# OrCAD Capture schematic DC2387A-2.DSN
size Custom; company: ANALOG DEVICES; note: DEMO BOARD BILL OF MATERIALS; note: 60VIN, 5A STEP-DOWN µMODULE REGULATOR
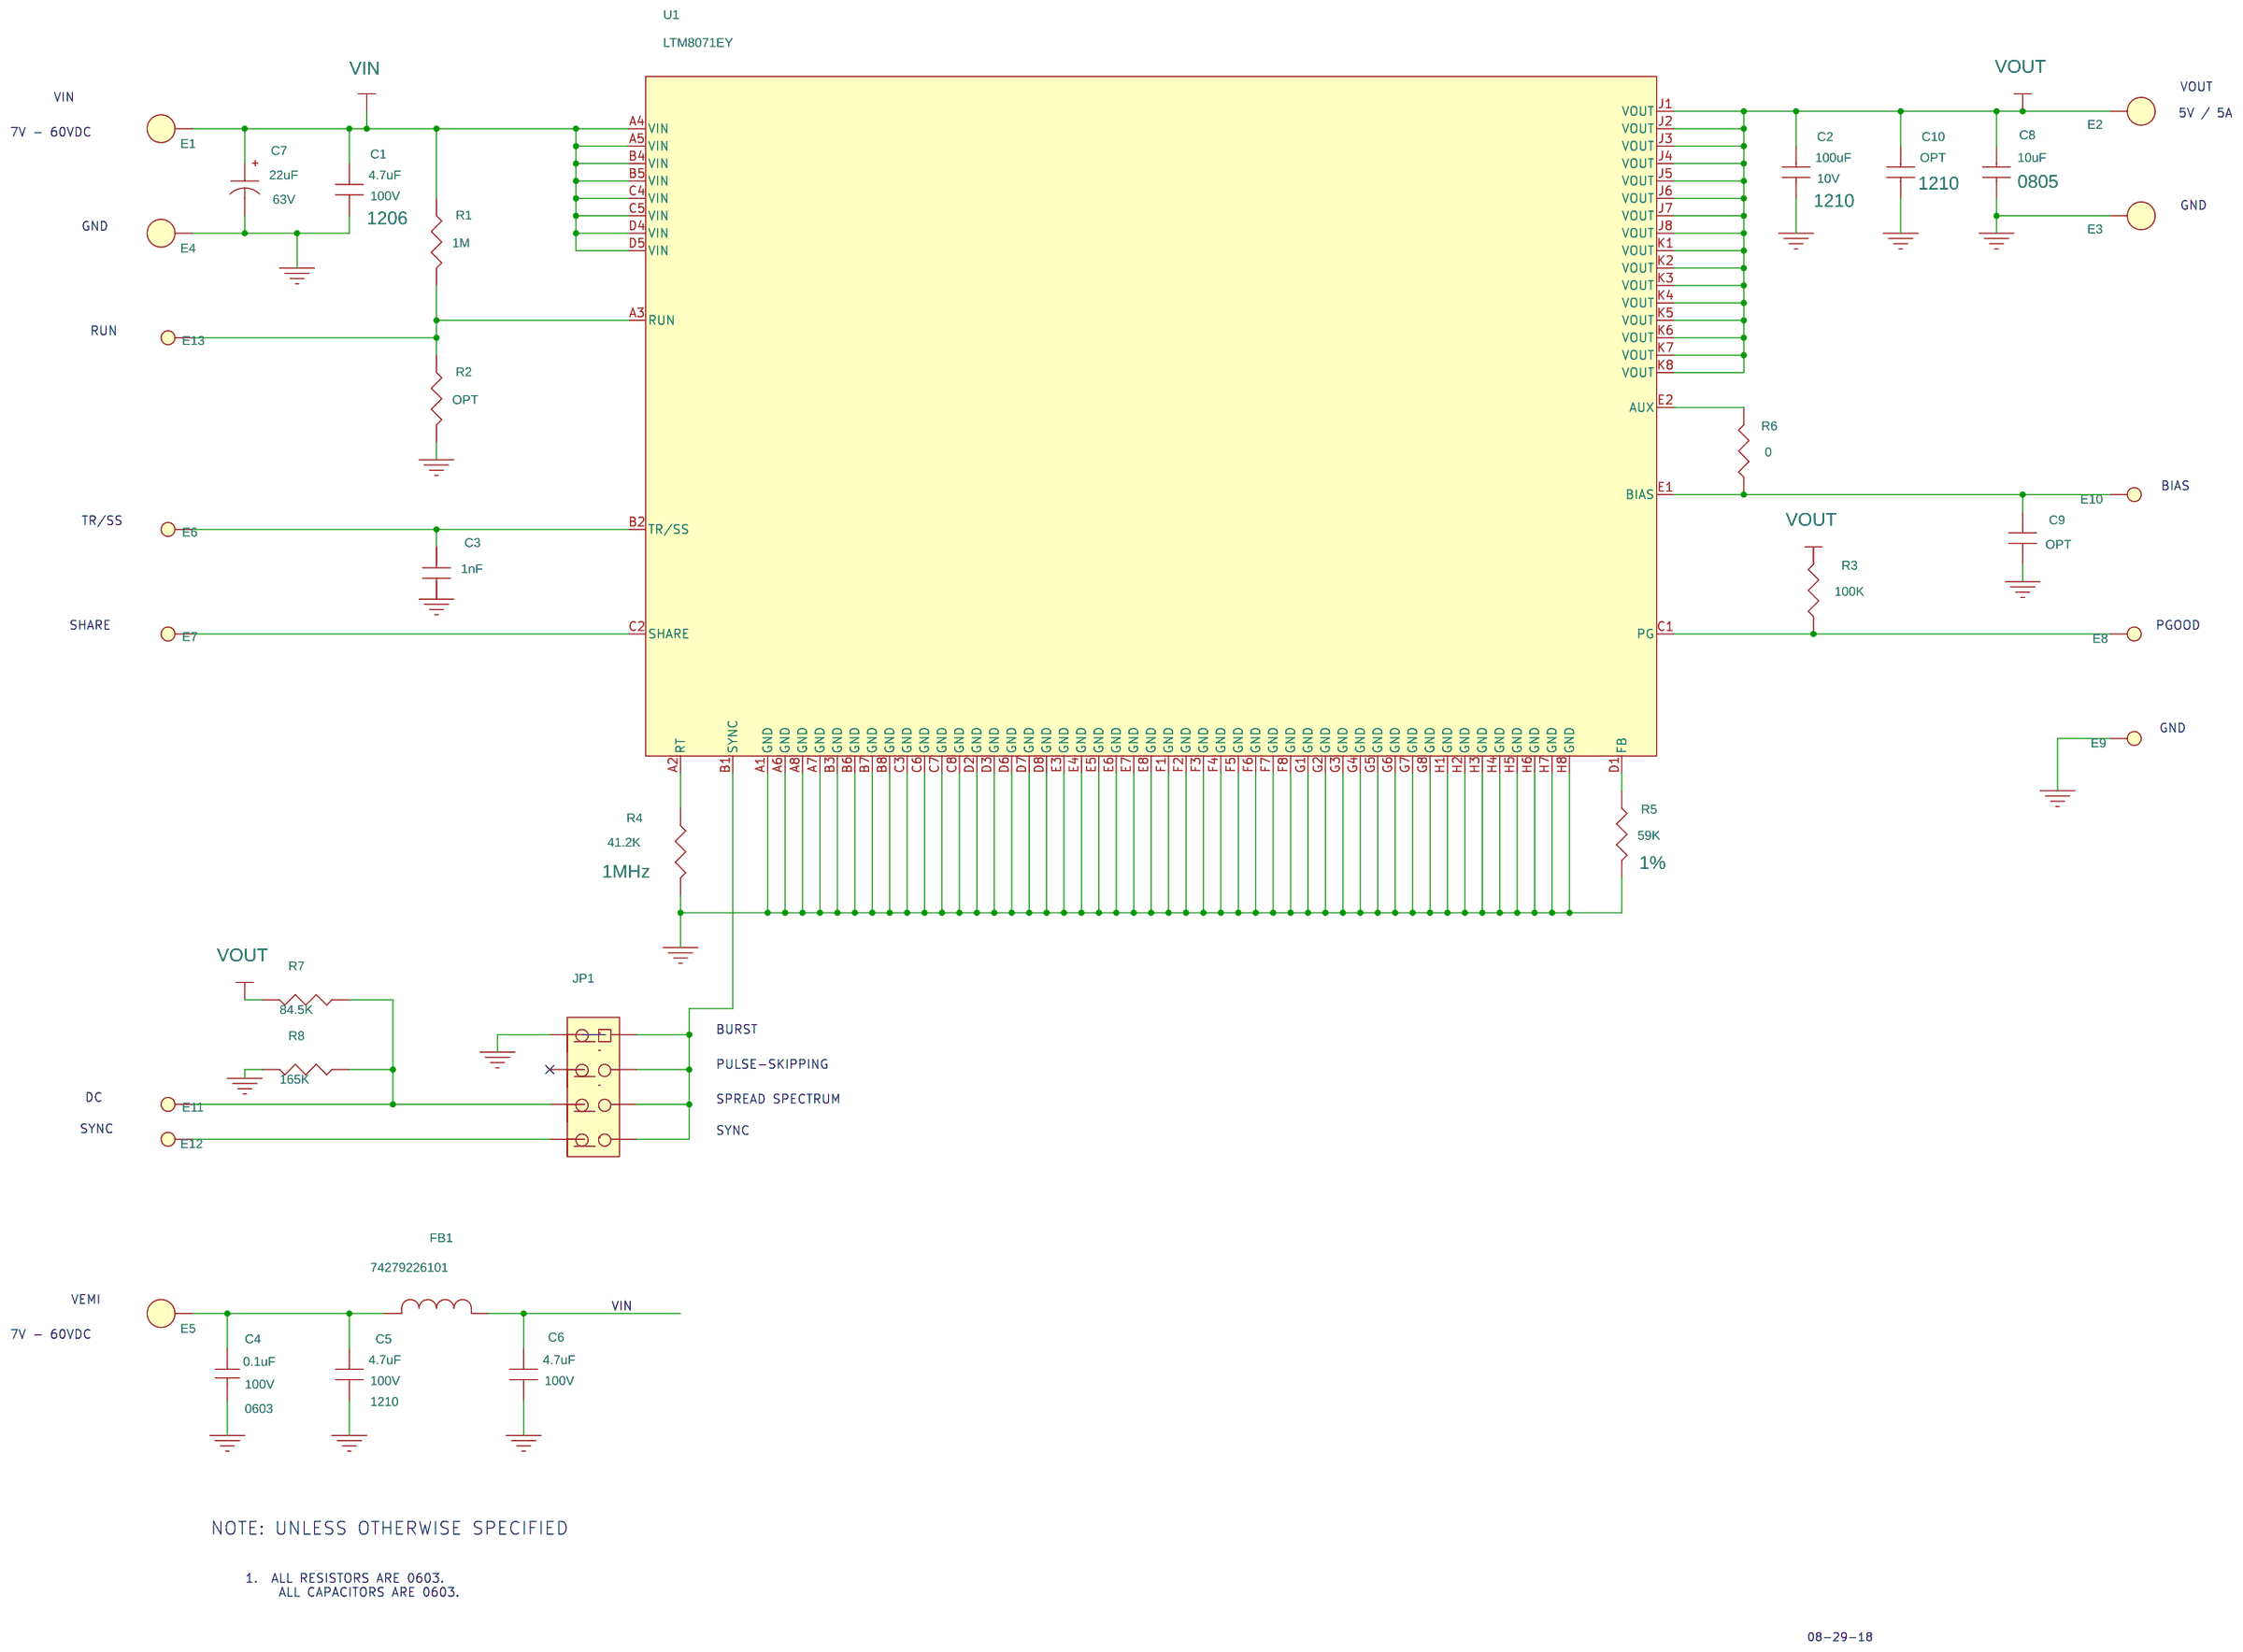
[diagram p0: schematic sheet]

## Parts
C1  4.7uF  [1206]
C2  100uF  [1210]
C3  1nF  [0603]
C4  0.1uF  [0603]
C5  4.7uF  [1210]
C6  4.7uF  [1210]
C7  22uF  [CAP-CE-BS-6.3X7.7]
C8  10uF  [0805]
C9  OPT  [0603]
C10  OPT  [1210]
E1  Testpoint  [MM/2501]
E2  Testpoint  [MM/2501]
E3  Testpoint  [MM/2501]
E4  Testpoint  [MM/2501]
E5  Testpoint  [MM/2501]
E6  -  [MM/2308]
E7  -  [MM/2308]
E8  -  [MM/2308]
E9  -  [MM/2308]
E10  -  [MM/2308]
E11  -  [MM/2308]
E12  -  [MM/2308]
E13  -  [MM/2308]
FB1  74279226101  [BEAD74279226101]
JP1  JP4X2/079/J  [JP4X2/079]
R1  1M  [0603]
R2  OPT  [0603]
R3  100K  [0603]
R4  41.2K  [0603]
R5  59K  [0603]
R6  0  [0603]
R7  84.5K  [0603]
R8  165K  [0603]
U1  LTM8071EY  [BGA-80]

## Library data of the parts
C1 C5 C6 = CAP1210: 1ST PART FIELD: 100V
C2 C10 = CAP1210: 1ST PART FIELD: 10V; 2nd Part Field: 1206; 5th Part Field: 1206; SIZE: 1206
C3 C8 C9 = CAP0402
C4 = CAP-NP: 1ST PART FIELD: 100V
C7 = CAP-CV-6.3X6: 1ST PART FIELD: 63V; 3RD PART FIELD: OPT
E1-E5 = MillMax-2501_0
E6-E13 = MillMax-2308(SM)
FB1 = IND-TOKO-DB320C: 4TH PART FIELD: Coilcraft,
JP1 = JP4X2_079_J
R1 R2 = AAC-0603
R3 R6-R8 = AAC-0402
R4 = AAC-0603: 2nd Part Field: 1MHz
R5 = AAC-0603: 2ND PART FIELD: 1%
U1 = LTM8071_2

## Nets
GND_POWER: C1.2 C2.2 C3.1 C4.2 C5.2 C6.2 C7.2 C8.1 C9.1 C10.2 E3.1 E4.1 E9.1 JP1.2 R2.2 R4.2 R5.2 R8.2 U1.A1(GND) U1.A6(GND) U1.A7(GND) U1.A8(GND) U1.B3(GND) U1.B6(GND) U1.B7(GND) U1.B8(GND) U1.C3(GND) U1.C6(GND) U1.C7(GND) U1.C8(GND) U1.D2(GND) U1.D3(GND) U1.D6(GND) U1.D7(GND) U1.D8(GND) U1.E3(GND) U1.E4(GND) U1.E5(GND) U1.E6(GND) U1.E7(GND) U1.E8(GND) U1.F1(GND) U1.F2(GND) U1.F3(GND) U1.F4(GND) U1.F5(GND) U1.F6(GND) U1.F7(GND) U1.F8(GND) U1.G1(GND) U1.G2(GND) U1.G3(GND) U1.G4(GND) U1.G5(GND) U1.G6(GND) U1.G7(GND) U1.G8(GND) U1.H1(GND) U1.H2(GND) U1.H3(GND) U1.H4(GND) U1.H5(GND) U1.H6(GND) U1.H7(GND) U1.H8(GND)
VIN: C1.1 C6.1 C7.1 E1.1 FB1.2 R1.1 U1.A4(VIN) U1.A5(VIN) U1.B4(VIN) U1.B5(VIN) U1.C4(VIN) U1.C5(VIN) U1.D4(VIN) U1.D5(VIN)
VOUT: C2.1 C8.2 C10.1 E2.1 R3.2 R7.2 U1.J1(VOUT) U1.J2(VOUT) U1.J3(VOUT) U1.J4(VOUT) U1.J5(VOUT) U1.J6(VOUT) U1.J7(VOUT) U1.J8(VOUT) U1.K1(VOUT) U1.K2(VOUT) U1.K3(VOUT) U1.K4(VOUT) U1.K5(VOUT) U1.K6(VOUT) U1.K7(VOUT) U1.K8(VOUT)
N874325: C9.2 E10.1 R6.1 U1.E1(BIAS)
N940753: E13.1 R1.2 R2.1 U1.A3(RUN)
N958764: C4.1 C5.1 E5.1 FB1.1
N962718: C3.2 E6.1 U1.B2(TR/SS)
N962971: E7.1 U1.C2(SHARE)
N963074: R4.1 U1.A2(RT)
N964632: R5.1 U1.D1(FB)
N965360: JP1.1 JP1.3 JP1.5 JP1.7 U1.B1(SYNC)
N965457: E12.1 JP1.8
N965461: E11.1 JP1.6 R7.1 R8.1
N966387: R6.2 U1.E2(AUX)
N966453: E8.1 R3.1 U1.C1(PG)

Not connected (* = marked no-connect by the designer): JP1 4*

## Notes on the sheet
- VIN
- VOUT
- 5V / 5A
- 7V - 60VDC
- GND
- GND
- RUN
- BIAS
- TR/SS
- SHARE
- PGOOD
- GND
- BURST
- PULSE-SKIPPING
- DC
- SPREAD SPECTRUM
- SYNC
- SYNC
- VEMI
- 7V - 60VDC
- NOTE: UNLESS OTHERWISE SPECIFIED
- 1.  ALL RESISTORS ARE 0603.
       ALL CAPACITORS ARE 0603.
- 08-29-18
